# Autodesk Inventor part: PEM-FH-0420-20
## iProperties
Created: 2009-01
Part Number: PEM-FH-0420-20
Document SubType Name: Modeling
Designer: claivier
Material: Acier
Norme de conversion: STEP AP214IS
Nom du fichier: PEM-FH-0420-20.STEP
Préprocesseur: SolidWorks 2008
Postprocesseur: Build: 344a, Release: 11 SP2 - Date: Fri 08/18/2006
Unités envoyées: INCHES
Incertitude: 1e-05
Author: claivier
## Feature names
1. Base1
